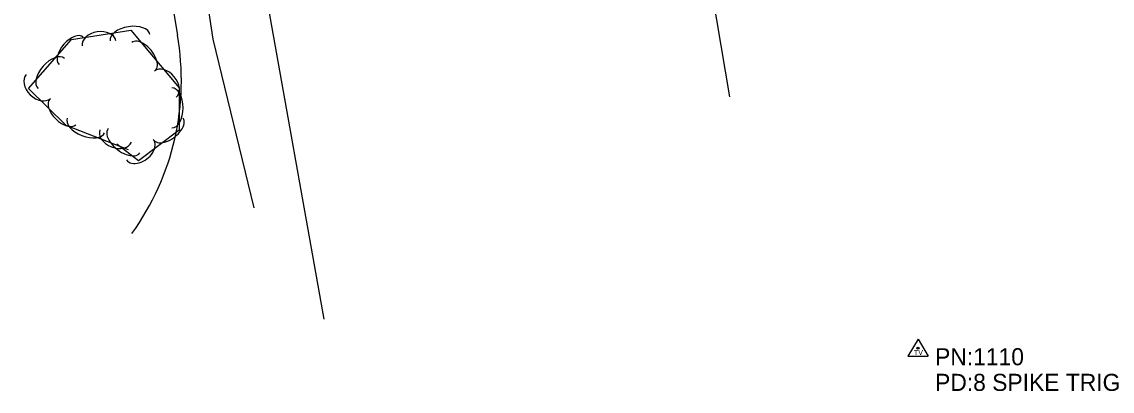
# Model space of a CAD drawing. Extents: x 1451369 to 1458940, y 1868647 to 1875095.
# Drawn here: x 1454038.8 to 1454358, y 1871014.3 to 1871122.4 of the extents above; entities that cross this region are included whole.
import ezdxf

# ---------------------------------------------------------------- set-up
doc = ezdxf.new("R2010")
doc.units = 0
for name, color, linetype in [('E_ROW Point Number', 7, 'Continuous'), ('E_Station Offset', 7, 'Continuous'), ('S_MISC_BOUNDARY', 7, 'Continuous'), ('S_PARKING', 7, 'Continuous'), ('S_SECONDARY_CTL_ANNOT', 7, 'Continuous')]:
    doc.layers.add(name, color=color, linetype=linetype)

msp = doc.modelspace()

# ---------------------------------------------------------------- linework, layer by layer
at = {"layer": 'E_ROW Point Number'}
msp.add_lwpolyline([(1454070, 1871084.92), (1454051.73, 1871092.09), (1454040.78, 1871102.91), (1454053.36, 1871117.23), (1454070.71, 1871119.93), (1454084.87, 1871103.02), (1454084.87, 1871090.67), (1454072.94, 1871081.67), (1454066.56, 1871086.54)], dxfattribs=at)
for centre, major_axis, ratio, start_param, end_param in [((1454053.26, 1871113.9), (-3.53, -4.02), 0.540667, 3.141593, 6.283185), ((1454061.37, 1871116.07), (-4.9, -0.76), 0.685226, 3.141593, 6.283185), ((1454070.48, 1871117.75), (-5.8, -0.9), 0.550012, 3.141593, 6.283185), ((1454074.41, 1871112.2), (-3.43, 4.1), 0.540674, 3.141585, 6.283178), ((1454047.41, 1871107.24), (-3.87, -4.41), 0.550047, 3.141593, 6.283185), ((1454080.83, 1871104.14), (-3.18, 3.8), 0.685279, 3.14158, 6.283172), ((1454043.62, 1871103.46), (3.52, -3.48), 0.68527, 3.141593, 6.283185), ((1454082.75, 1871097.21), (0, 5.87), 0.550094, 3.141596, 6.283188), ((1454050.76, 1871096.03), (3.8, -3.76), 0.540667, 3.141593, 6.283185), ((1454057.54, 1871092.09), (5.46, -2.14), 0.550022, 3.141593, 6.283185), ((1454081.74, 1871090.96), (4.27, 3.22), 0.540724, 3.141752, 6.283345), ((1454066.26, 1871088.95), (4.61, -1.81), 0.685238, 3.141593, 6.283185), ((1454068.71, 1871087.57), (4.66, -3.56), 0.550335, 3.14191, 6.283503), ((1454073.35, 1871084.97), (3.96, 2.98), 0.685342, 3.141862, 6.283455)]:
    msp.add_ellipse(centre, major_axis=major_axis, ratio=ratio, start_param=start_param, end_param=end_param, dxfattribs=at)
at = {"layer": 'E_Station Offset'}
for p, q in [((1454301.18, 1871029.52), (1454298.17, 1871024.56)), ((1454301.18, 1871029.52), (1454304.13, 1871024.56)), ((1454298.17, 1871024.56), (1454304.13, 1871024.56))]:
    msp.add_line(p, q, dxfattribs=at)
for radius in [0.311, 0.183, 0.103]:
    msp.add_circle((1454301.18, 1871026.91), radius, dxfattribs=at)
at = {"layer": 'S_MISC_BOUNDARY'}
msp.add_lwpolyline([(1454127.28, 1871035.4), (1454109.64, 1871134.41), (1454096.66, 1871194.27), (1454098.31, 1871211.51), (1454108.83, 1871220.36), (1454124.15, 1871222.22), (1454176.81, 1871211.33), (1454230.64, 1871191.17), (1454246.01, 1871100.39)], dxfattribs=at)
at = {"layer": 'S_PARKING'}
for points in [[(1454106.8, 1871068), (1454094.84, 1871117.33), (1454089.1, 1871154.74), (1454083.76, 1871181.06), (1454071.7, 1871220.04), (1454060.42, 1871252.14), (1454054.87, 1871269.35)], [(1454075.34, 1871172.14), (1454084.33, 1871118.48)]]:
    msp.add_lwpolyline(points, dxfattribs=at)
msp.add_ellipse((1454009.22, 1871105.18), major_axis=(27.99, 70.96), ratio=0.999964, start_param=4.462034, end_param=5.263366, dxfattribs=at)

# ---------------------------------------------------------------- texts
at = {"layer": 'E_Station Offset'}
msp.add_text('TV', height=1.5, rotation=360, dxfattribs=at).set_placement((1454299.98, 1871024.9))
at = {"layer": 'S_SECONDARY_CTL_ANNOT'}
for s, p in [('PN:1110', (1454306.18, 1871021.91)), ('PD:8 SPIKE TRIG ELEV', (1454306.18, 1871014.41))]:
    msp.add_text(s, height=5, dxfattribs=at).set_placement(p)

doc.saveas('drawing.dxf')
